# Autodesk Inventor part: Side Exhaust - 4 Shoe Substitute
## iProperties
Created: 2008-02
Part Number: Side Exhaust - 4 Shoe Substitute
Document SubType Name: Modeling
Designer: Autodesk, Inc.
Mass: 57.4848 g
Surface Area: 846.233 cm^2
Volume: 57.4848 cm^3
Density: 1 g/cm^3
Author: Autodesk, Inc.
